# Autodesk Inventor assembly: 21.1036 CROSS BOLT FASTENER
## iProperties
Created: 2006-12
Part Number: 21.1036 CROSS BOLT FASTENER
Document SubType Name: Assembly
Designer: Andy Moles
Author: Andy Moles
